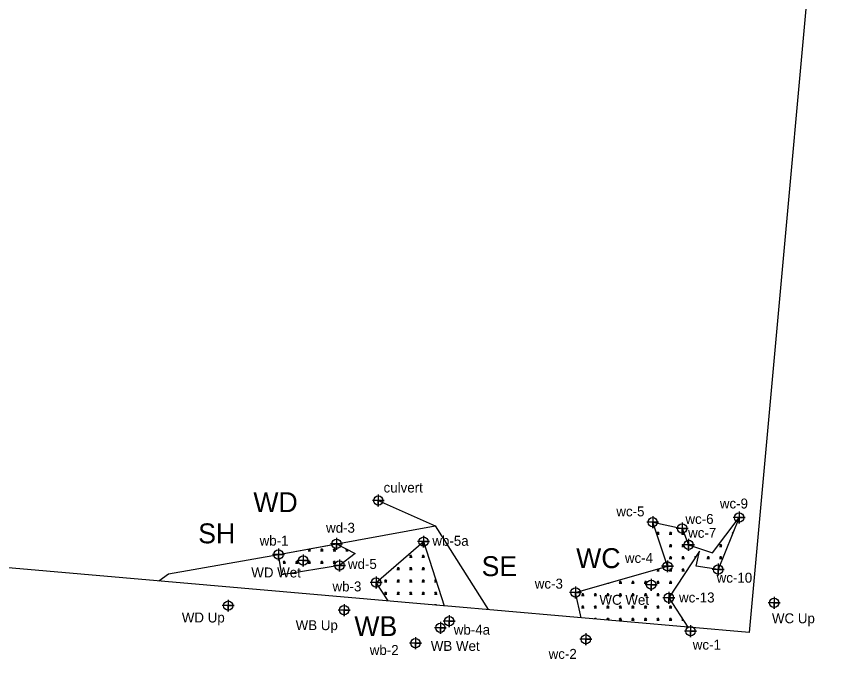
# Model space of a CAD drawing. Extents: x 1637473 to 1644249, y 841388 to 844031.
# Drawn here: x 1643836.1 to 1644249.1, y 841849.2 to 842182.7 of the extents above; entities that cross this region are included whole.
import ezdxf

# ---------------------------------------------------------------- set-up
doc = ezdxf.new("R2010")
doc.units = 0
for name, color, linetype in [('Default', 7, 'Continuous'), ('Default Symbol CELL', 7, 'Continuous'), ('Exist Environmental Wetland Boundary', 7, 'Continuous'), ('Exist Environmental Wetland Boundary Cogo Point CELL', 7, 'Continuous'), ('Exist Environmental Wetland Boundary Text', 7, 'Continuous'), ('Exist Hydro Jurisdictional Stream or Body of Water Mitigable', 7, 'Continuous'), ('Exist Hydro Jurisdictional Stream or Body of Water Mitigable Cogo Point CELL', 7, 'Continuous')]:
    doc.layers.add(name, color=color, linetype=linetype)

msp = doc.modelspace()

# ---------------------------------------------------------------- linework, layer by layer
at = {"layer": 'Default'}
msp.add_line((1644050.75, 841886.76), (1644050.41, 841886.79), dxfattribs=at)
for points in [[(1643123.93, 842470.88), (1644249.14, 842372.65), (1644203.72, 841873.41), (1644050.75, 841886.76)], [(1644050.41, 841886.79), (1643207.51, 841960.38), (1642457.5, 841546.57), (1642334.98, 841388.5), (1642010.83, 841639.74), (1641748.37, 841502.24), (1641281.09, 841734.92), (1641245.41, 841826.26), (1640567.36, 842176.47)]]:
    msp.add_lwpolyline(points, dxfattribs=at)
at = {"layer": 'Default Symbol CELL'}
for points in [[(1643980.03, 841912.44), (1643980.03, 841906.44), (1643980.03, 841909.44), (1643983.03, 841909.44), (1643977.03, 841909.44)], [(1644154.63, 841900.35), (1644154.63, 841894.35), (1644154.63, 841897.35), (1644157.63, 841897.35), (1644151.63, 841897.35)], [(1643942.41, 841889.83), (1643942.41, 841883.83), (1643942.41, 841886.83), (1643945.41, 841886.83), (1643939.41, 841886.83)], [(1644216.28, 841891.25), (1644216.28, 841885.25), (1644216.28, 841888.25), (1644219.28, 841888.25), (1644213.28, 841888.25)], [(1644000.52, 841887.59), (1644000.52, 841881.59), (1644000.52, 841884.59), (1644003.52, 841884.59), (1643997.52, 841884.59)], [(1644048.83, 841878.7), (1644048.83, 841872.7), (1644048.83, 841875.7), (1644051.83, 841875.7), (1644045.83, 841875.7)]]:
    msp.add_lwpolyline(points, dxfattribs=at)
for centre in [(1643980.03, 841909.44), (1644154.63, 841897.35), (1644216.28, 841888.25), (1643942.41, 841886.83), (1644000.52, 841884.59), (1644048.83, 841875.7)]:
    msp.add_circle(centre, 2.34, dxfattribs=at)
at = {"layer": 'Exist Environmental Wetland Boundary'}
for points in [[(1644119.48, 841880.76), (1644116.71, 841893.48), (1644162.8, 841906.58), (1644155.38, 841928.73), (1644170.15, 841925.61), (1644173.42, 841917.33), (1644185.39, 841913.29), (1644198.76, 841931.06), (1644188.29, 841904.96), (1644177.17, 841906.58), (1644178.79, 841914.22), (1644163.45, 841890.81), (1644172.99, 841876.09)], [(1644022.57, 841889.22), (1644016.62, 841898.41), (1644040.4, 841918.96), (1644050.78, 841886.76)]]:
    msp.add_lwpolyline(points, dxfattribs=at)
msp.add_lwpolyline([(1643998.17, 841907.02), (1643969.25, 841902.37), (1643967.6, 841912.49), (1643996.74, 841917.83), (1644006.11, 841913.03)], close=True, dxfattribs=at)
at = {"layer": 'Exist Environmental Wetland Boundary Cogo Point CELL'}
for points in [[(1644155.38, 841931.73), (1644155.38, 841925.73), (1644155.38, 841928.73), (1644158.38, 841928.73), (1644152.38, 841928.73)], [(1644198.76, 841934.06), (1644198.76, 841928.06), (1644198.76, 841931.06), (1644201.76, 841931.06), (1644195.76, 841931.06)], [(1644170.15, 841928.61), (1644170.15, 841922.61), (1644170.15, 841925.61), (1644173.15, 841925.61), (1644167.15, 841925.61)], [(1643996.72, 841920.84), (1643996.72, 841914.84), (1643996.72, 841917.84), (1643999.72, 841917.84), (1643993.72, 841917.84)], [(1644040.4, 841921.96), (1644040.4, 841915.96), (1644040.4, 841918.96), (1644043.4, 841918.96), (1644037.4, 841918.96)], [(1644173.42, 841920.33), (1644173.42, 841914.33), (1644173.42, 841917.33), (1644176.42, 841917.33), (1644170.42, 841917.33)], [(1643967.6, 841915.49), (1643967.6, 841909.49), (1643967.6, 841912.49), (1643970.6, 841912.49), (1643964.6, 841912.49)], [(1643998.17, 841910.02), (1643998.17, 841904.02), (1643998.17, 841907.02), (1644001.17, 841907.02), (1643995.17, 841907.02)], [(1644162.8, 841909.58), (1644162.8, 841903.58), (1644162.8, 841906.58), (1644165.8, 841906.58), (1644159.8, 841906.58)], [(1644188.29, 841907.96), (1644188.29, 841901.96), (1644188.29, 841904.96), (1644191.29, 841904.96), (1644185.29, 841904.96)], [(1644016.62, 841901.41), (1644016.62, 841895.41), (1644016.62, 841898.41), (1644019.62, 841898.41), (1644013.62, 841898.41)], [(1644116.71, 841896.48), (1644116.71, 841890.48), (1644116.71, 841893.48), (1644119.71, 841893.48), (1644113.71, 841893.48)], [(1644163.45, 841893.81), (1644163.45, 841887.81), (1644163.45, 841890.81), (1644166.45, 841890.81), (1644160.45, 841890.81)], [(1644053.27, 841882.02), (1644053.27, 841876.02), (1644053.27, 841879.02), (1644056.27, 841879.02), (1644050.27, 841879.02)], [(1644174.37, 841876.97), (1644174.37, 841870.97), (1644174.37, 841873.97), (1644177.37, 841873.97), (1644171.37, 841873.97)], [(1644121.83, 841872.93), (1644121.83, 841866.93), (1644121.83, 841869.93), (1644124.83, 841869.93), (1644118.83, 841869.93)], [(1644036.33, 841870.99), (1644036.33, 841864.99), (1644036.33, 841867.99), (1644039.33, 841867.99), (1644033.33, 841867.99)]]:
    msp.add_lwpolyline(points, dxfattribs=at)
for centre in [(1644155.38, 841928.73), (1644198.76, 841931.06), (1644170.15, 841925.61), (1643996.72, 841917.84), (1644040.4, 841918.96), (1644173.42, 841917.33), (1643967.6, 841912.49), (1643998.17, 841907.02), (1644162.8, 841906.58), (1644188.29, 841904.96), (1644016.62, 841898.41), (1644116.71, 841893.48), (1644163.45, 841890.81), (1644053.27, 841879.02), (1644174.37, 841873.97), (1644036.33, 841867.99), (1644121.83, 841869.93)]:
    msp.add_circle(centre, 2.34, dxfattribs=at)
at = {"layer": 'Exist Hydro Jurisdictional Stream or Body of Water Mitigable'}
for p, q in [((1644195.15, 841922.78), (1644195.44, 841922.78)), ((1644176.28, 841910.42), (1644176.3, 841910.42)), ((1644163.7, 841891.87), (1644164.14, 841891.87))]:
    msp.add_line(p, q, dxfattribs=at)
for points in [[(1644017.71, 841939.6), (1644046.25, 841926.95), (1644072.77, 841884.84)], [(1643907.58, 841899.26), (1643912.46, 841902.74), (1643967.6, 841912.49), (1644046.25, 841926.95)], [(1644157.41, 841922.78), (1644158.06, 841922.78), (1644158.06, 841923.97), (1644158.06, 841922.78), (1644158.7, 841922.78)], [(1644163.7, 841922.78), (1644164.35, 841922.78), (1644164.35, 841923.97), (1644164.35, 841922.78), (1644164.99, 841922.78)], [(1644169.99, 841922.78), (1644170.64, 841922.78), (1644170.64, 841923.97), (1644170.64, 841922.78), (1644171.27, 841922.78)], [(1644195.8, 841923.68), (1644195.8, 841923.97), (1644195.8, 841923.68)], [(1644039.62, 841917.33), (1644040.26, 841917.33), (1644040.26, 841918.52), (1644040.26, 841917.33), (1644040.91, 841917.33)], [(1643982.47, 841914.31), (1643983.12, 841914.31), (1643983.12, 841915.34)], [(1643983.12, 841915.34), (1643983.12, 841914.31), (1643983.76, 841914.31)], [(1643988.76, 841914.31), (1643989.41, 841914.31), (1643989.41, 841915.49), (1643989.41, 841914.31), (1643990.05, 841914.31)], [(1643995.05, 841914.31), (1643995.7, 841914.31), (1643995.7, 841915.49), (1643995.7, 841914.31), (1643996.34, 841914.31)], [(1644001.34, 841914.31), (1644001.99, 841914.31), (1644001.99, 841915.14)], [(1644001.99, 841915.14), (1644001.99, 841914.31), (1644002.63, 841914.31)], [(1644163.7, 841916.6), (1644164.35, 841916.6), (1644164.35, 841917.78), (1644164.35, 841916.6), (1644164.99, 841916.6)], [(1644169.99, 841916.6), (1644170.64, 841916.6), (1644170.64, 841917.78), (1644170.64, 841916.6), (1644171.28, 841916.6)], [(1644188.86, 841916.6), (1644189.51, 841916.6), (1644189.51, 841917.78), (1644189.51, 841916.6), (1644190.15, 841916.6)], [(1644033.33, 841911.15), (1644033.97, 841911.15), (1644033.97, 841912.33), (1644033.97, 841911.15), (1644034.62, 841911.15)], [(1644039.62, 841911.15), (1644040.26, 841911.15), (1644040.26, 841912.33), (1644040.26, 841911.15), (1644040.91, 841911.15)], [(1644163.7, 841910.42), (1644164.35, 841910.42), (1644164.35, 841911.6), (1644164.35, 841910.42), (1644164.99, 841910.42)], [(1644169.99, 841910.42), (1644170.64, 841910.42), (1644170.64, 841911.6), (1644170.64, 841910.42), (1644171.28, 841910.42)], [(1644176.93, 841911.38), (1644176.93, 841911.6), (1644176.93, 841911.38)], [(1644182.57, 841910.42), (1644183.22, 841910.42), (1644183.22, 841911.6), (1644183.22, 841910.42), (1644183.86, 841910.42)], [(1644188.86, 841910.42), (1644189.51, 841910.42), (1644189.51, 841911.6), (1644189.51, 841910.42), (1644190.15, 841910.42)], [(1643969.89, 841908.12), (1643970.54, 841908.12), (1643970.54, 841909.31), (1643970.54, 841908.12), (1643971.18, 841908.12)], [(1643976.18, 841908.12), (1643976.83, 841908.12), (1643976.83, 841909.31), (1643976.83, 841908.12), (1643977.47, 841908.12)], [(1643982.47, 841908.12), (1643983.12, 841908.12), (1643983.12, 841909.31), (1643983.12, 841908.12), (1643983.76, 841908.12)], [(1643988.76, 841908.12), (1643989.41, 841908.12), (1643989.41, 841909.31), (1643989.41, 841908.12), (1643990.05, 841908.12)], [(1643995.05, 841908.12), (1643995.7, 841908.12), (1643995.7, 841909.31), (1643995.7, 841908.12), (1643996.34, 841908.12)], [(1644027.04, 841904.97), (1644027.68, 841904.97), (1644027.68, 841906.15), (1644027.68, 841904.97), (1644028.33, 841904.97)], [(1644033.33, 841904.97), (1644033.97, 841904.97), (1644033.97, 841906.15), (1644033.97, 841904.97), (1644034.62, 841904.97)], [(1644039.62, 841904.97), (1644040.26, 841904.97), (1644040.26, 841906.15), (1644040.26, 841904.97), (1644040.91, 841904.97)], [(1643970.54, 841902.57), (1643970.54, 841903.12), (1643970.54, 841902.57)], [(1644157.41, 841904.23), (1644158.06, 841904.23), (1644158.06, 841905.24)], [(1644158.06, 841905.24), (1644158.06, 841904.23), (1644158.7, 841904.23)], [(1644163.7, 841904.23), (1644164.35, 841904.23), (1644164.35, 841905.42), (1644164.35, 841904.23), (1644164.99, 841904.23)], [(1644169.99, 841904.23), (1644170.64, 841904.23), (1644170.64, 841905.42), (1644170.64, 841904.23), (1644171.28, 841904.23)], [(1644020.75, 841898.78), (1644021.39, 841898.78), (1644021.39, 841899.97), (1644021.39, 841898.78), (1644022.04, 841898.78)], [(1644027.04, 841898.78), (1644027.68, 841898.78), (1644027.68, 841899.97), (1644027.68, 841898.78), (1644028.33, 841898.78)], [(1644033.33, 841898.78), (1644033.97, 841898.78), (1644033.97, 841899.97), (1644033.97, 841898.78), (1644034.62, 841898.78)], [(1644039.62, 841898.78), (1644040.26, 841898.78), (1644040.26, 841899.97), (1644040.26, 841898.78), (1644040.91, 841898.78)], [(1644045.91, 841898.78), (1644046.55, 841898.78), (1644046.55, 841899.87)], [(1644046.55, 841899.87), (1644046.55, 841898.78), (1644046.9, 841898.78)], [(1644132.78, 841898.05), (1644132.9, 841898.05), (1644132.9, 841898.08)], [(1644132.9, 841898.08), (1644132.9, 841898.05), (1644133.54, 841898.05)], [(1644138.54, 841898.05), (1644139.19, 841898.05), (1644139.19, 841899.23), (1644139.19, 841898.05), (1644139.83, 841898.05)], [(1644144.83, 841898.05), (1644145.48, 841898.05), (1644145.48, 841899.23), (1644145.48, 841898.05), (1644146.12, 841898.05)], [(1644151.12, 841898.05), (1644151.77, 841898.05), (1644151.77, 841899.23), (1644151.77, 841898.05), (1644152.41, 841898.05)], [(1644157.41, 841898.05), (1644158.06, 841898.05), (1644158.06, 841899.23), (1644158.06, 841898.05), (1644158.7, 841898.05)], [(1644163.7, 841898.05), (1644164.35, 841898.05), (1644164.35, 841899.23), (1644164.35, 841898.05), (1644164.99, 841898.05)], [(1644020.75, 841892.6), (1644021.39, 841892.6), (1644021.39, 841893.78), (1644021.39, 841892.6), (1644022.04, 841892.6)], [(1644027.04, 841892.6), (1644027.68, 841892.6), (1644027.68, 841893.78), (1644027.68, 841892.6), (1644028.33, 841892.6)], [(1644033.33, 841892.6), (1644033.97, 841892.6), (1644033.97, 841893.78), (1644033.97, 841892.6), (1644034.62, 841892.6)], [(1644039.62, 841892.6), (1644040.26, 841892.6), (1644040.26, 841893.78), (1644040.26, 841892.6), (1644040.91, 841892.6)], [(1644045.91, 841892.6), (1644046.55, 841892.6), (1644046.55, 841893.78), (1644046.55, 841892.6), (1644047.2, 841892.6)], [(1644119.67, 841891.87), (1644120.32, 841891.87), (1644120.32, 841893.05), (1644120.32, 841891.87), (1644120.96, 841891.87)], [(1644125.96, 841891.87), (1644126.61, 841891.87), (1644126.61, 841893.05), (1644126.61, 841891.87), (1644127.25, 841891.87)], [(1644132.25, 841891.87), (1644132.9, 841891.87), (1644132.9, 841893.05), (1644132.9, 841891.87), (1644133.54, 841891.87)], [(1644138.54, 841891.87), (1644139.19, 841891.87), (1644139.19, 841893.05), (1644139.19, 841891.87), (1644139.83, 841891.87)], [(1644144.83, 841891.87), (1644145.48, 841891.87), (1644145.48, 841893.05), (1644145.48, 841891.87), (1644146.12, 841891.87)], [(1644151.12, 841891.87), (1644151.77, 841891.87), (1644151.77, 841893.05), (1644151.77, 841891.87), (1644152.41, 841891.87)], [(1644157.41, 841891.87), (1644158.06, 841891.87), (1644158.06, 841893.05), (1644158.06, 841891.87), (1644158.7, 841891.87)], [(1644164.35, 841892.18), (1644164.35, 841893.05), (1644164.35, 841892.18)], [(1644046.55, 841887.13), (1644046.55, 841887.6), (1644046.55, 841887.13)], [(1644119.67, 841885.68), (1644120.32, 841885.68), (1644120.32, 841886.87), (1644120.32, 841885.68), (1644120.96, 841885.68)], [(1644125.96, 841885.68), (1644126.61, 841885.68), (1644126.61, 841886.87), (1644126.61, 841885.68), (1644127.25, 841885.68)], [(1644132.25, 841885.68), (1644132.9, 841885.68), (1644132.9, 841886.87), (1644132.9, 841885.68), (1644133.54, 841885.68)], [(1644138.54, 841885.68), (1644139.19, 841885.68), (1644139.19, 841886.87), (1644139.19, 841885.68), (1644139.83, 841885.68)], [(1644144.83, 841885.68), (1644145.48, 841885.68), (1644145.48, 841886.87), (1644145.48, 841885.68), (1644146.12, 841885.68)], [(1644151.12, 841885.68), (1644151.77, 841885.68), (1644151.77, 841886.87), (1644151.77, 841885.68), (1644152.41, 841885.68)], [(1644157.41, 841885.68), (1644158.06, 841885.68), (1644158.06, 841886.87), (1644158.06, 841885.68), (1644158.7, 841885.68)], [(1644163.7, 841885.68), (1644164.35, 841885.68), (1644164.35, 841886.87), (1644164.35, 841885.68), (1644164.99, 841885.68)], [(1644126.61, 841880.14), (1644126.61, 841880.68), (1644126.61, 841880.14)], [(1644132.9, 841879.59), (1644132.9, 841880.68), (1644132.9, 841879.59)], [(1644138.54, 841879.5), (1644139.19, 841879.5), (1644139.19, 841880.68), (1644139.19, 841879.5), (1644139.83, 841879.5)], [(1644144.83, 841879.5), (1644145.48, 841879.5), (1644145.48, 841880.68), (1644145.48, 841879.5), (1644146.12, 841879.5)], [(1644151.12, 841879.5), (1644151.77, 841879.5), (1644151.77, 841880.68), (1644151.77, 841879.5), (1644152.41, 841879.5)], [(1644157.41, 841879.5), (1644158.06, 841879.5), (1644158.06, 841880.68), (1644158.06, 841879.5), (1644158.7, 841879.5)], [(1644163.7, 841879.5), (1644164.35, 841879.5), (1644164.35, 841880.68), (1644164.35, 841879.5), (1644164.99, 841879.5)], [(1644169.99, 841879.5), (1644170.64, 841879.5), (1644170.64, 841879.72)], [(1644170.64, 841879.72), (1644170.64, 841879.5), (1644170.78, 841879.5)]]:
    msp.add_lwpolyline(points, dxfattribs=at)
for centre, radius, start, end in [((1644157.14, 841922.72), 0.922, 4.1403, 67.535), ((1644159.42, 841922.33), 1.44, 122.1274, 161.6222), ((1644163.43, 841922.72), 0.922, 4.1403, 67.535), ((1644165.72, 841922.33), 1.44, 122.1274, 161.6222), ((1644169.72, 841922.72), 0.922, 4.1403, 67.535), ((1644172.01, 841922.33), 1.44, 132.7638, 161.6222), ((1644194.88, 841922.72), 0.922, 35.5083, 67.535), ((1643982.2, 841914.24), 0.922, 4.1403, 67.535), ((1643984.48, 841913.85), 1.44, 122.1274, 161.6222), ((1643988.49, 841914.24), 0.922, 4.1403, 67.535), ((1643990.77, 841913.85), 1.44, 122.1274, 161.6222), ((1643994.78, 841914.24), 0.922, 4.1403, 67.535), ((1643997.06, 841913.85), 1.44, 122.1274, 161.6222), ((1644001.07, 841914.24), 0.922, 4.1403, 67.535), ((1644003.35, 841913.85), 1.44, 131.6641, 161.6222), ((1644039.34, 841917.27), 0.922, 4.1403, 67.535), ((1644041.63, 841916.88), 1.44, 129.625, 161.6222), ((1644163.43, 841916.53), 0.922, 4.1403, 67.535), ((1644165.72, 841916.15), 1.44, 122.1274, 161.6222), ((1644169.72, 841916.53), 0.922, 4.1403, 67.535), ((1644172.01, 841916.15), 1.44, 122.1274, 161.6222), ((1644188.59, 841916.53), 0.922, 4.1403, 67.535), ((1644190.88, 841916.15), 1.44, 122.1274, 161.6222), ((1644033.05, 841911.08), 0.922, 4.1403, 67.535), ((1644035.34, 841910.7), 1.44, 122.1274, 161.6222), ((1644039.34, 841911.08), 0.922, 4.1403, 67.535), ((1644041.63, 841910.7), 1.44, 122.1274, 161.6222), ((1644163.43, 841910.35), 0.922, 4.1403, 67.535), ((1644165.72, 841909.96), 1.44, 122.1274, 161.6222), ((1644169.72, 841910.35), 0.922, 4.1403, 67.535), ((1644172.01, 841909.96), 1.44, 122.1274, 161.6222), ((1644176.01, 841910.35), 0.922, 43.8921, 67.535), ((1644182.3, 841910.35), 0.922, 4.1403, 67.535), ((1644184.59, 841909.96), 1.44, 122.1274, 161.6222), ((1644188.59, 841910.35), 0.922, 4.1403, 67.535), ((1644190.88, 841909.96), 1.44, 122.1274, 161.6222), ((1643969.62, 841908.06), 0.922, 4.1403, 67.535), ((1643971.9, 841907.67), 1.44, 122.1274, 161.6222), ((1643975.91, 841908.06), 0.922, 4.1403, 67.535), ((1643978.19, 841907.67), 1.44, 122.1274, 161.6222), ((1643982.2, 841908.06), 0.922, 4.1403, 67.535), ((1643984.48, 841907.67), 1.44, 122.1274, 161.6222), ((1643988.49, 841908.06), 0.922, 4.1403, 67.535), ((1643990.77, 841907.67), 1.44, 122.1274, 161.6222), ((1643994.78, 841908.06), 0.922, 4.1403, 67.535), ((1643997.06, 841907.67), 1.44, 122.1274, 161.6222), ((1643969.62, 841901.87), 0.922, 45.5037, 67.535), ((1643971.9, 841901.48), 1.44, 122.1274, 125.3576), ((1644026.76, 841904.9), 0.922, 4.1403, 67.535), ((1644029.05, 841904.51), 1.44, 122.1274, 161.6222), ((1644033.05, 841904.9), 0.922, 4.1403, 67.535), ((1644035.34, 841904.51), 1.44, 122.1274, 161.6222), ((1644039.34, 841904.9), 0.922, 4.1403, 67.535), ((1644041.63, 841904.51), 1.44, 122.1274, 161.6222), ((1644157.14, 841904.17), 0.922, 4.1403, 67.535), ((1644159.42, 841903.78), 1.44, 122.1274, 161.6222), ((1644163.43, 841904.17), 0.922, 4.1403, 67.535), ((1644165.72, 841903.78), 1.44, 122.1274, 161.6222), ((1644169.72, 841904.17), 0.922, 4.1403, 67.535), ((1644172.01, 841903.78), 1.44, 122.1274, 161.6222), ((1644020.47, 841898.72), 0.922, 4.1403, 67.535), ((1644022.76, 841898.33), 1.44, 122.1274, 161.6222), ((1644026.76, 841898.72), 0.922, 4.1403, 67.535), ((1644029.05, 841898.33), 1.44, 122.1274, 161.6222), ((1644033.05, 841898.72), 0.922, 4.1403, 67.535), ((1644035.34, 841898.33), 1.44, 122.1274, 161.6222), ((1644039.34, 841898.72), 0.922, 4.1403, 67.535), ((1644041.63, 841898.33), 1.44, 122.1274, 161.6222), ((1644045.63, 841898.72), 0.922, 4.1403, 67.535), ((1644047.92, 841898.33), 1.44, 143.0243, 161.6222), ((1644131.98, 841897.98), 0.922, 4.1403, 6.1685), ((1644134.26, 841897.6), 1.44, 160.0653, 161.6222), ((1644138.27, 841897.98), 0.922, 4.1403, 67.535), ((1644140.55, 841897.6), 1.44, 122.1274, 161.6222), ((1644144.56, 841897.98), 0.922, 4.1403, 67.535), ((1644146.84, 841897.6), 1.44, 122.1274, 161.6222), ((1644150.85, 841897.98), 0.922, 4.1403, 67.535), ((1644153.13, 841897.6), 1.44, 122.1274, 161.6222), ((1644157.14, 841897.98), 0.922, 4.1403, 67.535), ((1644159.42, 841897.6), 1.44, 122.1274, 161.6222), ((1644163.43, 841897.98), 0.922, 4.1403, 67.535), ((1644165.72, 841897.6), 1.44, 122.1274, 161.6222), ((1644020.47, 841892.53), 0.922, 4.1403, 67.535), ((1644022.76, 841892.14), 1.44, 122.1274, 161.6222), ((1644026.76, 841892.53), 0.922, 4.1403, 67.535), ((1644029.05, 841892.14), 1.44, 122.1274, 161.6222), ((1644033.05, 841892.53), 0.922, 4.1403, 67.535), ((1644035.34, 841892.14), 1.44, 122.1274, 161.6222), ((1644039.34, 841892.53), 0.922, 4.1403, 67.535), ((1644041.63, 841892.14), 1.44, 122.1274, 161.6222), ((1644045.63, 841892.53), 0.922, 4.1403, 67.535), ((1644047.92, 841892.14), 1.44, 122.1274, 161.6222), ((1644119.4, 841891.8), 0.922, 4.1403, 67.535), ((1644121.68, 841891.41), 1.44, 122.1274, 161.6222), ((1644125.69, 841891.8), 0.922, 4.1403, 67.535), ((1644127.97, 841891.41), 1.44, 122.1274, 161.6222), ((1644131.98, 841891.8), 0.922, 4.1403, 67.535), ((1644134.26, 841891.41), 1.44, 122.1274, 161.6222), ((1644138.27, 841891.8), 0.922, 4.1403, 67.535), ((1644140.55, 841891.41), 1.44, 122.1274, 161.6222), ((1644144.56, 841891.8), 0.922, 4.1403, 67.535), ((1644146.84, 841891.41), 1.44, 122.1274, 161.6222), ((1644150.85, 841891.8), 0.922, 4.1403, 67.535), ((1644153.13, 841891.41), 1.44, 122.1274, 161.6222), ((1644157.14, 841891.8), 0.922, 4.1403, 67.535), ((1644159.42, 841891.41), 1.44, 122.1274, 161.6222), ((1644163.43, 841891.8), 0.922, 19.1991, 67.535), ((1644045.63, 841886.35), 0.922, 63.0345, 67.535), ((1644047.92, 841885.96), 1.44, 122.1274, 128.6802), ((1644119.4, 841885.62), 0.922, 4.1403, 67.535), ((1644121.68, 841885.23), 1.44, 122.1274, 161.6222), ((1644125.69, 841885.62), 0.922, 4.1403, 67.535), ((1644127.97, 841885.23), 1.44, 122.1274, 161.6222), ((1644131.98, 841885.62), 0.922, 4.1403, 67.535), ((1644134.26, 841885.23), 1.44, 122.1274, 161.6222), ((1644138.27, 841885.62), 0.922, 4.1403, 67.535), ((1644140.55, 841885.23), 1.44, 122.1274, 161.6222), ((1644144.56, 841885.62), 0.922, 4.1403, 67.535), ((1644146.84, 841885.23), 1.44, 122.1274, 161.6222), ((1644150.85, 841885.62), 0.922, 4.1403, 67.535), ((1644153.13, 841885.23), 1.44, 122.1274, 161.6222), ((1644157.14, 841885.62), 0.922, 4.1403, 67.535), ((1644159.42, 841885.23), 1.44, 122.1274, 161.6222), ((1644163.43, 841885.62), 0.922, 4.1403, 67.535), ((1644165.72, 841885.23), 1.44, 122.1274, 161.6222), ((1644125.69, 841879.43), 0.922, 52.994, 67.535), ((1644127.97, 841879.05), 1.44, 122.1274, 132.7498), ((1644131.98, 841879.43), 0.922, 9.77, 67.535), ((1644134.26, 841879.05), 1.44, 122.1274, 157.9712), ((1644138.27, 841879.43), 0.922, 4.1403, 67.535), ((1644140.55, 841879.05), 1.44, 122.1274, 161.6222), ((1644144.56, 841879.43), 0.922, 4.1403, 67.535), ((1644146.84, 841879.05), 1.44, 122.1274, 161.6222), ((1644150.85, 841879.43), 0.922, 4.1403, 67.535), ((1644153.13, 841879.05), 1.44, 122.1274, 161.6222), ((1644157.14, 841879.43), 0.922, 4.1403, 67.535), ((1644159.42, 841879.05), 1.44, 122.1274, 161.6222), ((1644163.43, 841879.43), 0.922, 4.1403, 67.535), ((1644165.72, 841879.05), 1.44, 122.1274, 161.6222), ((1644169.72, 841879.43), 0.922, 4.1403, 67.535), ((1644172.01, 841879.05), 1.44, 155.6527, 161.6222)]:
    msp.add_arc(centre, radius, start, end, dxfattribs=at)
at = {"layer": 'Exist Hydro Jurisdictional Stream or Body of Water Mitigable Cogo Point CELL'}
msp.add_lwpolyline([(1644017.71, 841942.6), (1644017.71, 841936.6), (1644017.71, 841939.6), (1644020.71, 841939.6), (1644014.71, 841939.6)], dxfattribs=at)
msp.add_circle((1644017.71, 841939.6), 2.34, dxfattribs=at)

# ---------------------------------------------------------------- texts
at = {"layer": 'Default'}
for s, p in [('WD Wet', (1643953.97, 841900.99)), ('WC Wet', (1644128.66, 841887.25)), ('WD Up', (1643919.11, 841878.38)), ('WC Up', (1644215.21, 841877.98)), ('WB Up', (1643976.23, 841874.53)), ('WB Wet', (1644044.05, 841864.1))]:
    msp.add_text(s, height=5, dxfattribs=at).set_placement(p)
at = {"layer": 'Exist Environmental Wetland Boundary Text'}
for s, height, p in [('culvert', 5, (1644020.36, 841943.64)), ('WD', 10, (1643954.99, 841933.77)), ('wc-9', 5, (1644189.08, 841935.62)), ('wc-5', 5, (1644137.14, 841931.65)), ('wc-6', 5, (1644171.81, 841927.86)), ('SH', 10, (1643927.33, 841918.12)), ('wd-3', 5, (1643991.49, 841923.44)), ('wc-7', 5, (1644173.15, 841920.9)), ('wb-1', 5, (1643958.16, 841916.99)), ('wb-5a', 5, (1644044.82, 841916.89)), ('WC', 10, (1644116.97, 841905.68)), ('wd-5', 5, (1644002.46, 841905.27)), ('SE', 10, (1644069.54, 841901.65)), ('wc-4', 5, (1644141.45, 841908.3)), ('wc-10', 5, (1644187.47, 841898.36)), ('wb-3', 5, (1643994.72, 841893.98)), ('wc-3', 5, (1644096.21, 841895.38)), ('wc-13', 5, (1644168.59, 841888.43)), ('WB', 10, (1644005.68, 841871.54)), ('wb-4a', 5, (1644055.57, 841872.26)), ('wc-1', 5, (1644175.49, 841864.73)), ('wb-2', 5, (1644013.42, 841862.05)), ('wc-2', 5, (1644103.17, 841860.11))]:
    msp.add_text(s, height=height, dxfattribs=at).set_placement(p)

doc.saveas('drawing.dxf')
